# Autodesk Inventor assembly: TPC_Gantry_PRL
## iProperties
Shininess: 64.0
Length Units: 11272
Angle Units: 11279
Time Units: 11290
Mass Units: 11286
Length Display Precision: 3
Angle Display Precision: 2
Compacted: True
Part Number: TPC_Gantry_PRL
Document SubType Name: Assembly
Created: 2004-08
Designer: Lori
Manufacturer: Standard
Standards Organization: Custom
Density: 0.0
Volumn: 0.0
Area: 0.0
PropertySet Name: Model Information
Control State: 0
Master: False
Checked Out: False
Author: Lori
